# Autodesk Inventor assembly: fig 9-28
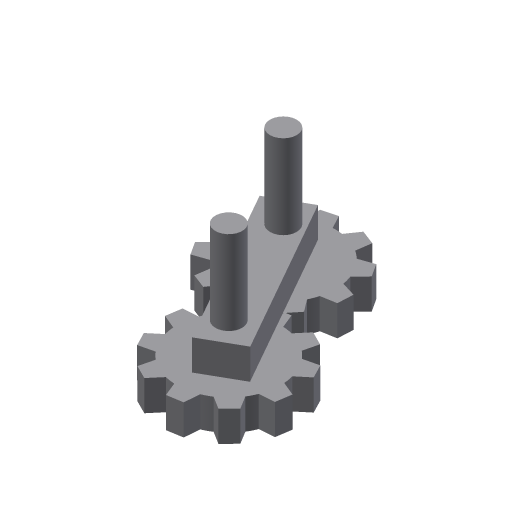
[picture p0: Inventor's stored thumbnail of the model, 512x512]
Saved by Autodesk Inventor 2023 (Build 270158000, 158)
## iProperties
Created: 2017-05
Part Number: fig 9-28
Document SubType Name: Assembly
Designer: CADCIM 00
Author: CADCIM 00
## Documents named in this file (3)
- D:\PROJECTS\Project 2022\Autodesk Inventor For Professional 2023\RESOURCES INVENTOR 2023\RESOURCES INVENTOR 2023\Inventor_2023_Part\Inventor_2023_Part\c09_Inv_2023_prt\fig 9-28.iam
- D:\PROJECTS\Project 2022\Autodesk Inventor For Professional 2023\RESOURCES INVENTOR 2023\RESOURCES INVENTOR 2023\Inventor_2023_Part\Inventor_2023_Part\c09_Inv_2023_prt\1.ipt
- D:\PROJECTS\Project 2022\Autodesk Inventor For Professional 2023\RESOURCES INVENTOR 2023\RESOURCES INVENTOR 2023\Inventor_2023_Part\Inventor_2023_Part\c09_Inv_2023_prt\2.ipt
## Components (3 placed, 2 different names)
1. 1:1 — Flush:1, Rotation:1, Insert:2
2. 1:2 — Flush:1, Rotation:1, Insert:1
3. 2:1 — Insert:1, Insert:2
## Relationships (4: Insert 2, Flush 1, RelateRotation 1)
- Flush:1: 1:1 ↔ 1:2
- Rotation:1 [RelateRotation]: 1:1 ↔ 1:2
- Insert:1: 1:2 ↔ 2:1
- Insert:2: 1:1 ↔ 2:1
